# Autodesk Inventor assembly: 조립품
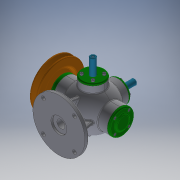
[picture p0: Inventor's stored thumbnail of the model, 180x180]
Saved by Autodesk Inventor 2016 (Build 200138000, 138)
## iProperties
Created: 2019-11
Part Number: 조립품
Material: 일반
Document SubType Name: Assembly
Designer: user
Author: user
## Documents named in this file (17)
- C:\Users\user\Desktop\391120V1002\조립품.iam
- C:\Users\user\Desktop\391120V1002\V-벨트풀리.ipt
- C:\Users\user\Desktop\391120V1002\너트 M8x1.ipt
- C:\Users\user\Desktop\391120V1002\뒤커버.ipt
- C:\Users\user\Desktop\391120V1002\베어링 6202.ipt
- C:\Users\user\Desktop\391120V1002\본체.ipt
- C:\Users\user\Desktop\391120V1002\본체커버.ipt
- C:\Users\user\Desktop\391120V1002\볼트 M4.ipt
- C:\Users\user\Desktop\391120V1002\스프링1.ipt
- C:\Users\user\Desktop\391120V1002\스프링2.ipt
- C:\Users\user\Desktop\391120V1002\슬라이드 커버.ipt
- C:\Users\user\Desktop\391120V1002\슬라이드.ipt
- C:\Users\user\Desktop\391120V1002\앞커버.ipt
- C:\Users\user\Desktop\391120V1002\오일 실.ipt
- C:\Users\user\Desktop\391120V1002\와셔 8x17.ipt
- C:\Users\user\Desktop\391120V1002\축.ipt
- C:\Users\user\Desktop\391120V1002\키 4x4.ipt
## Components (1 placed, 1 different names)
1. V-벨트풀리:1
